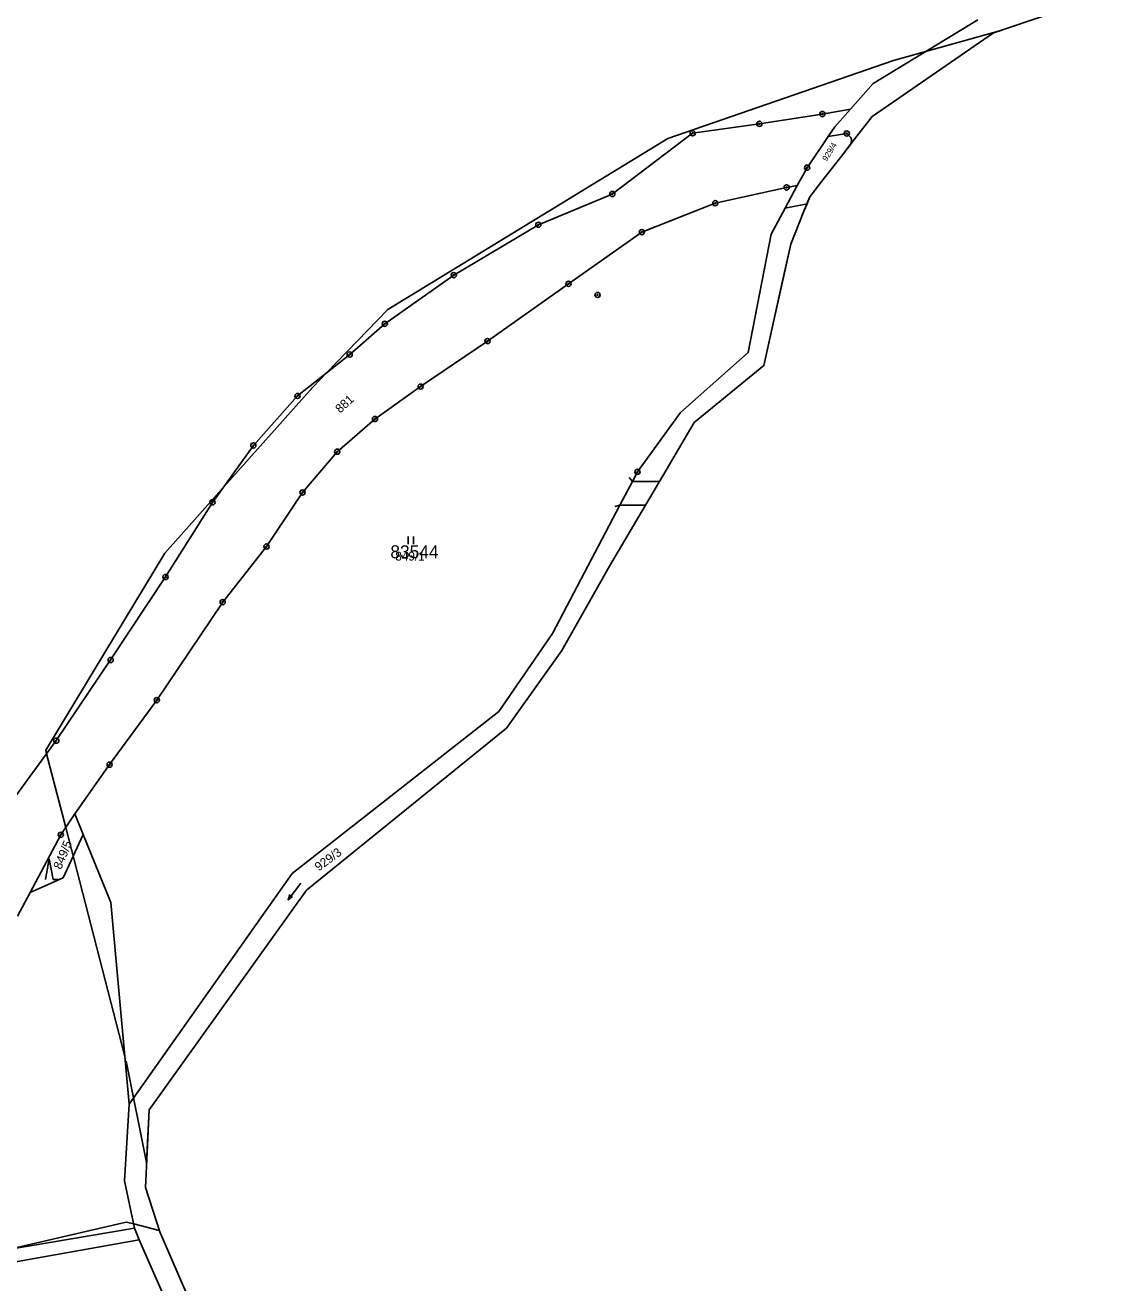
# Model space of a CAD drawing. Extents: x -547623 to -538651, y -1096714 to -1086522.
# Drawn here: x -543243.5 to -543035.4, y -1088531.7 to -1088289.2 of the extents above; entities that cross this region are included whole.
import ezdxf

# ---------------------------------------------------------------- set-up
doc = ezdxf.new("R2010")
doc.units = 0
for name, color, linetype in [('Vrstva 1', 7, 'Continuous'), ('Vrstva 25', 7, 'Continuous'), ('Vrstva 33', 7, 'Continuous'), ('Vrstva 40', 7, 'Continuous'), ('Vrstva 41', 7, 'Continuous'), ('Vrstva 52', 7, 'Continuous'), ('Vrstva 53', 7, 'Continuous'), ('Vrstva 83', 7, 'Continuous'), ('Vrstva 86', 7, 'Continuous')]:
    doc.layers.add(name, color=color, linetype=linetype)

msp = doc.modelspace()

# ---------------------------------------------------------------- linework, layer by layer
at = {"layer": 'Vrstva 1'}
for p, q in [((-543087.31, -1088308.75), (-543088.6, -1088310.65)), ((-543088.6, -1088310.65), (-543092.66, -1088316.65)), ((-543085, -1088310.05), (-543088.6, -1088310.65)), ((-543084.24, -1088310.8), (-543085, -1088310.05)), ((-543084.32, -1088312.19), (-543084.02, -1088311.43)), ((-543084.02, -1088311.43), (-543084.24, -1088310.8)), ((-543096.91, -1088324.45), (-543094.55, -1088320.08)), ((-543096.91, -1088324.45), (-543092.67, -1088323.59)), ((-543099.61, -1088329.44), (-543096.91, -1088324.45)), ((-543232.27, -1088445.28), (-543233.91, -1088441.28)), ((-543242.5, -1088456.41), (-543236.6, -1088445.31)), ((-543232.27, -1088445.28), (-543236.12, -1088453.64)), ((-543226.91, -1088458.38), (-543232.27, -1088445.28)), ((-543242.5, -1088456.41), (-543236.12, -1088453.64)), ((-543244.93, -1088460.98), (-543242.5, -1088456.41))]:
    msp.add_line(p, q, dxfattribs=at)
for points in [[(-543059.72, -1088288.13), (-543079.89, -1088300.39)], [(-543079.89, -1088300.39), (-543084.31, -1088305.36)], [(-543089.73, -1088306.3), (-543101.87, -1088308.2)], [(-543089.73, -1088306.3), (-543084.31, -1088305.36)], [(-543084.31, -1088305.36), (-543087.31, -1088308.75)], [(-543101.87, -1088308.2), (-543114.73, -1088310.01)], [(-543114.73, -1088310.01), (-543130.23, -1088321.73)], [(-543092.66, -1088316.65), (-543094.55, -1088320.08)], [(-543110.37, -1088323.51), (-543096.61, -1088320.47)], [(-543096.61, -1088320.47), (-543094.55, -1088320.08)], [(-543130.23, -1088321.73), (-543144.49, -1088327.65)], [(-543124.52, -1088329.08), (-543110.37, -1088323.51)], [(-543144.49, -1088327.65), (-543160.8, -1088337.37)], [(-543138.66, -1088339.04), (-543124.52, -1088329.08)], [(-543099.61, -1088329.44), (-543104, -1088352.3)], [(-543160.8, -1088337.37), (-543174.11, -1088346.76)], [(-543154.29, -1088350.09), (-543138.66, -1088339.04)], [(-543174.11, -1088346.76), (-543180.88, -1088352.69)], [(-543167.2, -1088358.87), (-543154.29, -1088350.09)], [(-543180.88, -1088352.69), (-543190.93, -1088360.67)], [(-543104, -1088352.3), (-543117.07, -1088363.84)], [(-543176, -1088365.12), (-543167.2, -1088358.87)], [(-543190.93, -1088360.67), (-543199.45, -1088370.22)], [(-543117.07, -1088363.84), (-543125.37, -1088375.32)], [(-543183.28, -1088371.43), (-543176, -1088365.12)], [(-543199.45, -1088370.22), (-543207.35, -1088381.2)], [(-543189.97, -1088379.28), (-543183.28, -1088371.43)], [(-543125.37, -1088375.32), (-543126.35, -1088377.18)], [(-543196.91, -1088389.72), (-543189.97, -1088379.28)], [(-543128.76, -1088381.75), (-543126.35, -1088377.18)], [(-543207.35, -1088381.2), (-543216.39, -1088395.59)], [(-543128.76, -1088381.75), (-543141.79, -1088406.47)], [(-543205.37, -1088400.43), (-543196.91, -1088389.72)], [(-543216.39, -1088395.59), (-543226.98, -1088411.59)], [(-543218.07, -1088419.33), (-543205.37, -1088400.43)], [(-543141.79, -1088406.47), (-543152.1, -1088421.55)], [(-543226.98, -1088411.59), (-543237.46, -1088427.15)], [(-543227.18, -1088431.78), (-543218.07, -1088419.33)], [(-543152.1, -1088421.55), (-543191.97, -1088452.77)], [(-543245.78, -1088438.52), (-543237.46, -1088427.15)], [(-543233.91, -1088441.28), (-543227.18, -1088431.78)], [(-543236.6, -1088445.31), (-543233.91, -1088441.28)], [(-543223.42, -1088497.24), (-543191.97, -1088452.77)], [(-543226.91, -1088458.38), (-543223.42, -1088497.24)], [(-543223.42, -1088497.24), (-543224.3, -1088512.08)], [(-543224.3, -1088512.08), (-543222.35, -1088521.16)], [(-543259.29, -1088527.4), (-543222.35, -1088521.16)], [(-543222.35, -1088521.16), (-543221.5, -1088523.44)], [(-543259.76, -1088530.23), (-543221.5, -1088523.44)], [(-543221.5, -1088523.44), (-543216.34, -1088535.11)]]:
    msp.add_lwpolyline(points, dxfattribs=at)
at = {"layer": 'Vrstva 25'}
for p, q in [((-543169.58, -1088389.25), (-543169.58, -1088387.75)), ((-543168.58, -1088389.25), (-543168.58, -1088387.75))]:
    msp.add_line(p, q, dxfattribs=at)
for points in [[(-543239.54, -1088453.93), (-543238.84, -1088449.93), (-543238.04, -1088453.93), (-543237.04, -1088453.93)], [(-543190.33, -1088454.64), (-543192.75, -1088457.84), (-543191.88, -1088457.24)], [(-543192.75, -1088457.84), (-543192.41, -1088456.84)]]:
    msp.add_lwpolyline(points, dxfattribs=at)
at = {"layer": 'Vrstva 33'}
for points in [[(-543121.12, -1088377.18), (-543126.35, -1088377.18)], [(-543123.81, -1088381.75), (-543128.76, -1088381.75)]]:
    msp.add_lwpolyline(points, dxfattribs=at)
at = {"layer": 'Vrstva 40'}
for p, q in [((-543126.35, -1088377.18), (-543126.96, -1088376.39)), ((-543128.76, -1088381.75), (-543129.73, -1088381.97))]:
    msp.add_line(p, q, dxfattribs=at)
at = {"layer": 'Vrstva 41'}
for p, q in [((-543093.26, -1088325.05), (-543092.67, -1088323.59)), ((-543092.67, -1088323.59), (-543092.18, -1088322.38))]:
    msp.add_line(p, q, dxfattribs=at)
for points in [[(-543056.69, -1088290.67), (-543035.43, -1088283.45)], [(-543076.01, -1088303.92), (-543056.69, -1088290.67)], [(-543080.13, -1088306.75), (-543076.01, -1088303.92)], [(-543083.54, -1088311.17), (-543080.13, -1088306.75)], [(-543084.32, -1088312.19), (-543083.54, -1088311.17)], [(-543085.78, -1088314.08), (-543084.32, -1088312.19)], [(-543089.8, -1088319.28), (-543087.18, -1088315.89)], [(-543087.18, -1088315.89), (-543085.78, -1088314.08)], [(-543092.18, -1088322.38), (-543091.28, -1088321.21)], [(-543091.28, -1088321.21), (-543089.8, -1088319.28)], [(-543095.82, -1088331.42), (-543093.26, -1088325.05)], [(-543100.99, -1088354.83), (-543095.82, -1088331.42)], [(-543114.41, -1088365.77), (-543100.99, -1088354.83)], [(-543121.12, -1088377.18), (-543114.41, -1088365.77)], [(-543123.81, -1088381.75), (-543121.12, -1088377.18)], [(-543130.74, -1088393.52), (-543123.81, -1088381.75)], [(-543139.96, -1088409.78), (-543130.74, -1088393.52)], [(-543150.65, -1088424.76), (-543139.96, -1088409.78)], [(-543189.22, -1088456.01), (-543150.65, -1088424.76)], [(-543219.56, -1088498.35), (-543189.22, -1088456.01)], [(-543220.28, -1088513.32), (-543219.56, -1088498.35)], [(-543217.52, -1088521.87), (-543220.28, -1088513.32)], [(-543212.27, -1088533.91), (-543217.52, -1088521.87)]]:
    msp.add_lwpolyline(points, dxfattribs=at)
at = {"layer": 'Vrstva 52'}
for points in [[(-543055.27, -1088290.19), (-543076, -1088296), (-543119.5, -1088311), (-543173.5, -1088344), (-543185.27, -1088356.18), (-543188, -1088359), (-543205.58, -1088378.73), (-543216.5, -1088391), (-543239.5, -1088429), (-543239.32, -1088429.69), (-543235.65, -1088443.89), (-543224.25, -1088488.05), (-543224.14, -1088489.2), (-543224, -1088489), (-543220.05, -1088508.5)], [(-543055.27, -1088290.19), (-543056.69, -1088290.67), (-543076.01, -1088303.92), (-543080.13, -1088306.75), (-543083.54, -1088311.17), (-543084.27, -1088312.12), (-543085.78, -1088314.08), (-543087.18, -1088315.89), (-543089.8, -1088319.28), (-543091.28, -1088321.21), (-543092.18, -1088322.38), (-543093.26, -1088325.05), (-543095.82, -1088331.42), (-543097.07, -1088337.06), (-543100.99, -1088354.83), (-543114.41, -1088365.77), (-543121.12, -1088377.18), (-543123.81, -1088381.75), (-543130.74, -1088393.52), (-543139.96, -1088409.78), (-543150.65, -1088424.76), (-543189.22, -1088456.01)], [(-543189.22, -1088456.01), (-543219.56, -1088498.35), (-543220.05, -1088508.5)], [(-543217.61, -1088521.6), (-543222.52, -1088520.37), (-543224, -1088520), (-543246.76, -1088525.28), (-543252, -1088526.5), (-543253.31, -1088526.39), (-543263.61, -1088525.53), (-543270.86, -1088524.93), (-543277.17, -1088521.91), (-543278.43, -1088519.13), (-543279.76, -1088516.19), (-543285.5, -1088503.5), (-543288.18, -1088488.76), (-543293.45, -1088459.78)], [(-543217.61, -1088521.6), (-543217.52, -1088521.87), (-543213.18, -1088531.83)]]:
    msp.add_lwpolyline(points, dxfattribs=at)
at = {"layer": 'Vrstva 83'}
for centre, radius in [((-543089.73, -1088306.3), 0.5), ((-543089.73, -1088306.3), 0.1), ((-543101.87, -1088308.2), 0.5), ((-543101.87, -1088308.2), 0.1), ((-543114.73, -1088310.01), 0.5), ((-543114.73, -1088310.01), 0.1), ((-543085, -1088310.05), 0.5), ((-543085, -1088310.05), 0.1), ((-543092.66, -1088316.65), 0.5), ((-543092.66, -1088316.65), 0.1), ((-543130.23, -1088321.73), 0.5), ((-543096.61, -1088320.47), 0.5), ((-543096.61, -1088320.47), 0.1), ((-543130.23, -1088321.73), 0.1), ((-543110.37, -1088323.51), 0.5), ((-543110.37, -1088323.51), 0.1), ((-543144.49, -1088327.65), 0.5), ((-543144.49, -1088327.65), 0.1), ((-543124.52, -1088329.08), 0.5), ((-543124.52, -1088329.08), 0.1), ((-543160.8, -1088337.37), 0.5), ((-543160.8, -1088337.37), 0.1), ((-543138.66, -1088339.04), 0.5), ((-543138.66, -1088339.04), 0.1), ((-543133.08, -1088341.19), 0.5), ((-543133.08, -1088341.19), 0.1), ((-543174.11, -1088346.76), 0.5), ((-543174.11, -1088346.76), 0.1), ((-543154.29, -1088350.09), 0.5), ((-543154.29, -1088350.09), 0.1), ((-543180.88, -1088352.69), 0.5), ((-543180.88, -1088352.69), 0.1), ((-543167.2, -1088358.87), 0.5), ((-543167.2, -1088358.87), 0.1), ((-543190.93, -1088360.67), 0.5), ((-543190.93, -1088360.67), 0.1), ((-543176, -1088365.12), 0.5), ((-543176, -1088365.12), 0.1), ((-543199.45, -1088370.22), 0.5), ((-543199.45, -1088370.22), 0.1), ((-543183.28, -1088371.43), 0.5), ((-543183.28, -1088371.43), 0.1), ((-543125.37, -1088375.32), 0.5), ((-543125.37, -1088375.32), 0.1), ((-543189.97, -1088379.28), 0.5), ((-543189.97, -1088379.28), 0.1), ((-543207.35, -1088381.2), 0.5), ((-543207.35, -1088381.2), 0.1), ((-543196.91, -1088389.72), 0.5), ((-543196.91, -1088389.72), 0.1), ((-543216.39, -1088395.59), 0.5), ((-543216.39, -1088395.59), 0.1), ((-543205.37, -1088400.43), 0.5), ((-543205.37, -1088400.43), 0.1), ((-543226.98, -1088411.59), 0.5), ((-543226.98, -1088411.59), 0.1), ((-543218.07, -1088419.33), 0.5), ((-543218.07, -1088419.33), 0.1), ((-543237.46, -1088427.15), 0.5), ((-543237.46, -1088427.15), 0.1), ((-543227.18, -1088431.78), 0.5), ((-543227.18, -1088431.78), 0.1), ((-543236.6, -1088445.31), 0.5), ((-543236.6, -1088445.31), 0.1)]:
    msp.add_circle(centre, radius, dxfattribs=at)

# ---------------------------------------------------------------- texts
at = {"layer": 'Vrstva 53'}
msp.add_text('83544', height=2.5, dxfattribs=at).set_placement((-543173.03, -1088391.98))
at = {"layer": 'Vrstva 86'}
for s, height, rotation, p in [('929/4', 1.14, 58.5, (-543088.86, -1088315.5)), ('881', 1.7, 42.3625, (-543182.71, -1088364.09)), ('849/5', 1.7, 67.5, (-543236.54, -1088452.12)), ('929/3', 1.7, 36, (-543186.85, -1088452.4))]:
    msp.add_text(s, height=height, rotation=rotation, dxfattribs=at).set_placement(p)
msp.add_text('849/1', height=1.7, dxfattribs=at).set_placement((-543172.09, -1088392.42))

doc.saveas('drawing.dxf')
